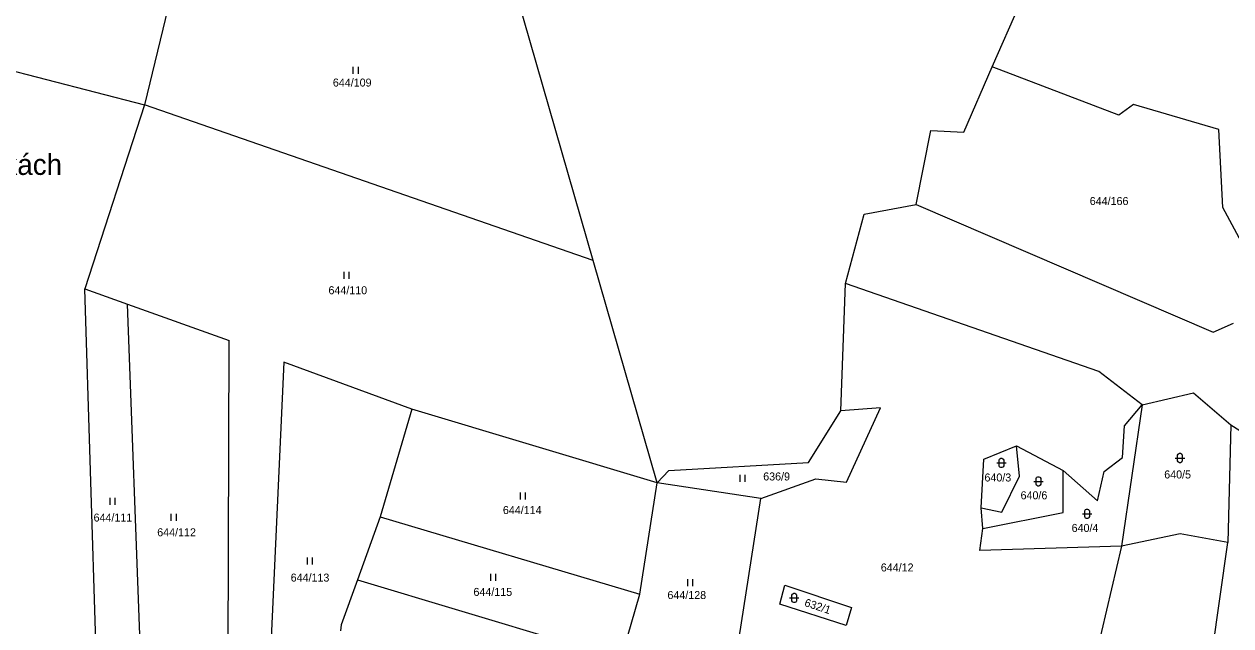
# Model space of a CAD drawing. Extents: x -791032 to -787751, y -1106872 to -1104403.
# Drawn here: x -789189 to -788932.6, y -1105599.2 to -1105471.5 of the extents above; entities that cross this region are included whole.
import ezdxf

# ---------------------------------------------------------------- set-up
doc = ezdxf.new("R2010")
doc.units = 0
for name, color, linetype in [('Vrstva 1', 7, 'Continuous'), ('Vrstva 14', 7, 'Continuous'), ('Vrstva 23', 7, 'Continuous'), ('Vrstva 39', 7, 'Continuous')]:
    doc.layers.add(name, color=color, linetype=linetype)

msp = doc.modelspace()

# ---------------------------------------------------------------- linework, layer by layer
at = {"layer": 'Vrstva 1'}
for p, q in [((-789146.23, -1105417.04), (-789163.41, -1105488.56)), ((-789068.11, -1105521.62), (-789084.1, -1105466)), ((-788983.32, -1105480.53), (-788977.5, -1105467.19)), ((-789221.79, -1105473.54), (-789163.41, -1105488.56)), ((-788989.37, -1105494.38), (-788983.32, -1105480.53)), ((-788956.44, -1105490.81), (-788983.32, -1105480.53)), ((-789163.41, -1105488.56), (-789176.09, -1105527.61)), ((-789068.11, -1105521.62), (-789163.41, -1105488.56)), ((-788953.33, -1105488.52), (-788956.44, -1105490.81)), ((-788935.16, -1105493.81), (-788953.33, -1105488.52)), ((-788999.5, -1105509.74), (-788996.37, -1105494.01)), ((-788996.37, -1105494.01), (-788989.37, -1105494.38)), ((-788934.33, -1105510.37), (-788935.16, -1105493.81)), ((-789010.51, -1105511.8), (-788999.5, -1105509.74)), ((-788999.5, -1105509.74), (-788936.39, -1105536.82)), ((-788925.08, -1105527.62), (-788934.33, -1105510.37)), ((-789014.53, -1105526.51), (-789010.51, -1105511.8)), ((-789054.54, -1105568.84), (-789068.11, -1105521.62)), ((-789015.5, -1105553.54), (-789014.53, -1105526.51)), ((-788960.67, -1105545.22), (-789014.53, -1105526.51)), ((-789176.09, -1105527.61), (-789167.02, -1105530.86)), ((-789173.21, -1105621.57), (-789176.09, -1105527.61)), ((-789163.6, -1105624.48), (-789167.02, -1105530.86)), ((-789167.02, -1105530.86), (-789145.48, -1105538.58)), ((-788936.39, -1105536.82), (-788932.05, -1105534.93)), ((-789145.77, -1105629.87), (-789145.48, -1105538.58)), ((-789133.84, -1105543.23), (-789137.95, -1105632.24)), ((-789106.67, -1105553.19), (-789133.84, -1105543.23)), ((-788951.45, -1105552.28), (-788960.67, -1105545.22)), ((-788951.45, -1105552.28), (-788940.6, -1105549.7)), ((-788940.6, -1105549.7), (-788932.67, -1105556.52)), ((-788951.45, -1105552.28), (-788955.9, -1105582.27)), ((-788955.22, -1105556.74), (-788951.45, -1105552.28)), ((-789106.67, -1105553.19), (-789113.4, -1105576.03)), ((-789054.54, -1105568.84), (-789106.67, -1105553.19)), ((-789022.35, -1105564.49), (-789015.5, -1105553.54)), ((-789007.06, -1105552.9), (-789015.5, -1105553.54)), ((-789014.27, -1105568.64), (-789007.06, -1105552.9)), ((-788955.67, -1105563.47), (-788955.22, -1105556.74)), ((-788932.67, -1105556.52), (-788933.29, -1105581.46)), ((-788932.67, -1105556.52), (-788924.39, -1105561.67)), ((-788985.13, -1105563.76), (-788978.18, -1105560.93)), ((-788977.52, -1105567.42), (-788978.18, -1105560.93)), ((-788978.18, -1105560.93), (-788968.25, -1105566.19)), ((-789052.03, -1105566.22), (-789022.35, -1105564.49)), ((-788985.68, -1105574.1), (-788985.13, -1105563.76)), ((-788959.53, -1105566.4), (-788955.67, -1105563.47)), ((-789054.54, -1105568.84), (-789052.03, -1105566.22)), ((-788981.32, -1105575.01), (-788977.52, -1105567.42)), ((-788968.27, -1105575.09), (-788968.25, -1105566.19)), ((-788968.25, -1105566.19), (-788960.99, -1105572.65)), ((-788960.99, -1105572.65), (-788959.53, -1105566.4)), ((-789058.19, -1105592.46), (-789054.54, -1105568.84)), ((-789032.47, -1105572.13), (-789054.54, -1105568.84)), ((-789032.47, -1105572.13), (-789020.83, -1105567.98)), ((-789020.83, -1105567.98), (-789014.27, -1105568.64)), ((-789038.51, -1105610.64), (-789032.47, -1105572.13)), ((-788985.33, -1105578.53), (-788985.68, -1105574.1)), ((-788985.68, -1105574.1), (-788981.32, -1105575.01)), ((-788985.33, -1105578.53), (-788968.27, -1105575.09)), ((-789113.4, -1105576.03), (-789118.21, -1105589.38)), ((-789113.4, -1105576.03), (-789058.19, -1105592.46)), ((-788985.96, -1105583.19), (-788985.33, -1105578.53)), ((-788943.38, -1105579.67), (-788955.9, -1105582.27)), ((-788933.29, -1105581.46), (-788943.38, -1105579.67)), ((-788955.9, -1105582.27), (-788985.96, -1105583.19)), ((-788955.9, -1105582.27), (-788969.53, -1105640.88)), ((-788941.4, -1105638.01), (-788933.29, -1105581.46)), ((-789118.21, -1105589.38), (-789121.66, -1105598.94)), ((-789118.21, -1105589.38), (-789073.82, -1105602.7)), ((-789028.45, -1105594.59), (-789027.41, -1105590.51)), ((-789027.41, -1105590.51), (-789013.24, -1105595.25)), ((-789061.77, -1105604.7), (-789058.19, -1105592.46)), ((-789014.39, -1105599.12), (-789028.45, -1105594.59)), ((-789013.24, -1105595.25), (-789014.39, -1105599.12)), ((-789121.66, -1105598.94), (-789121.78, -1105600.2))]:
    msp.add_line(p, q, dxfattribs=at)
at = {"layer": 'Vrstva 23'}
for p, q in [((-789119.07, -1105482.01), (-789119.07, -1105480.51)), ((-789118.07, -1105480.51), (-789118.07, -1105482.01)), ((-789120.99, -1105525.54), (-789120.99, -1105524.04)), ((-789119.99, -1105524.04), (-789119.99, -1105525.54)), ((-788943.75, -1105562.65), (-788943.55, -1105562.55)), ((-788943.55, -1105562.55), (-788943.35, -1105562.55)), ((-788943.35, -1105562.55), (-788943.15, -1105562.65)), ((-788982.39, -1105564.59), (-788980.39, -1105564.59)), ((-788981.89, -1105563.99), (-788981.79, -1105563.79)), ((-788981.89, -1105565.19), (-788981.89, -1105563.99)), ((-788981.79, -1105565.39), (-788981.89, -1105565.19)), ((-788981.79, -1105563.79), (-788981.69, -1105563.69)), ((-788981.69, -1105563.69), (-788981.49, -1105563.59)), ((-788981.49, -1105563.59), (-788981.29, -1105563.59)), ((-788981.29, -1105563.59), (-788981.09, -1105563.69)), ((-788981.09, -1105563.69), (-788980.99, -1105563.79)), ((-788980.99, -1105563.79), (-788980.89, -1105563.99)), ((-788980.89, -1105565.19), (-788980.99, -1105565.39)), ((-788980.89, -1105563.99), (-788980.89, -1105565.19)), ((-788944.45, -1105563.55), (-788942.45, -1105563.55)), ((-788943.95, -1105562.95), (-788943.85, -1105562.75)), ((-788943.95, -1105564.15), (-788943.95, -1105562.95)), ((-788943.85, -1105564.35), (-788943.95, -1105564.15)), ((-788943.85, -1105562.75), (-788943.75, -1105562.65)), ((-788943.75, -1105564.45), (-788943.85, -1105564.35)), ((-788943.55, -1105564.55), (-788943.75, -1105564.45)), ((-788943.35, -1105564.55), (-788943.55, -1105564.55)), ((-788943.15, -1105564.45), (-788943.35, -1105564.55)), ((-788943.15, -1105562.65), (-788943.05, -1105562.75)), ((-788943.05, -1105564.35), (-788943.15, -1105564.45)), ((-788943.05, -1105562.75), (-788942.95, -1105562.95)), ((-788942.95, -1105564.15), (-788943.05, -1105564.35)), ((-788942.95, -1105562.95), (-788942.95, -1105564.15)), ((-789036.86, -1105568.63), (-789036.86, -1105567.13)), ((-789035.86, -1105567.13), (-789035.86, -1105568.63)), ((-788981.69, -1105565.49), (-788981.79, -1105565.39)), ((-788981.49, -1105565.59), (-788981.69, -1105565.49)), ((-788981.29, -1105565.59), (-788981.49, -1105565.59)), ((-788981.09, -1105565.49), (-788981.29, -1105565.59)), ((-788980.99, -1105565.39), (-788981.09, -1105565.49)), ((-788974.03, -1105567.91), (-788973.93, -1105567.71)), ((-788973.93, -1105567.71), (-788973.83, -1105567.61)), ((-788973.83, -1105567.61), (-788973.63, -1105567.51)), ((-788973.63, -1105567.51), (-788973.43, -1105567.51)), ((-788973.43, -1105567.51), (-788973.23, -1105567.61)), ((-788973.23, -1105567.61), (-788973.13, -1105567.71)), ((-788973.13, -1105567.71), (-788973.03, -1105567.91)), ((-788974.53, -1105568.51), (-788972.53, -1105568.51)), ((-788974.03, -1105569.11), (-788974.03, -1105567.91)), ((-788973.93, -1105569.31), (-788974.03, -1105569.11)), ((-788973.83, -1105569.41), (-788973.93, -1105569.31)), ((-788973.63, -1105569.51), (-788973.83, -1105569.41)), ((-788973.43, -1105569.51), (-788973.63, -1105569.51)), ((-788973.23, -1105569.41), (-788973.43, -1105569.51)), ((-788973.13, -1105569.31), (-788973.23, -1105569.41)), ((-788973.03, -1105569.11), (-788973.13, -1105569.31)), ((-788973.03, -1105567.91), (-788973.03, -1105569.11)), ((-789170.74, -1105573.52), (-789170.74, -1105572.02)), ((-789169.74, -1105572.02), (-789169.74, -1105573.52)), ((-789083.58, -1105572.37), (-789083.58, -1105570.87)), ((-789082.58, -1105570.87), (-789082.58, -1105572.37)), ((-789157.74, -1105576.91), (-789157.74, -1105575.41)), ((-789156.74, -1105575.41), (-789156.74, -1105576.91)), ((-788964.19, -1105575.39), (-788962.19, -1105575.39)), ((-788963.69, -1105574.79), (-788963.59, -1105574.59)), ((-788963.69, -1105575.99), (-788963.69, -1105574.79)), ((-788963.59, -1105574.59), (-788963.49, -1105574.49)), ((-788963.49, -1105574.49), (-788963.29, -1105574.39)), ((-788963.29, -1105574.39), (-788963.09, -1105574.39)), ((-788963.09, -1105574.39), (-788962.89, -1105574.49)), ((-788962.89, -1105574.49), (-788962.79, -1105574.59)), ((-788962.79, -1105574.59), (-788962.69, -1105574.79)), ((-788962.69, -1105574.79), (-788962.69, -1105575.99)), ((-788963.59, -1105576.19), (-788963.69, -1105575.99)), ((-788963.49, -1105576.29), (-788963.59, -1105576.19)), ((-788963.29, -1105576.39), (-788963.49, -1105576.29)), ((-788963.09, -1105576.39), (-788963.29, -1105576.39)), ((-788962.89, -1105576.29), (-788963.09, -1105576.39)), ((-788962.79, -1105576.19), (-788962.89, -1105576.29)), ((-788962.69, -1105575.99), (-788962.79, -1105576.19)), ((-789128.82, -1105586.15), (-789128.82, -1105584.65)), ((-789127.82, -1105584.65), (-789127.82, -1105586.15)), ((-789089.88, -1105589.61), (-789089.88, -1105588.11)), ((-789088.88, -1105588.11), (-789088.88, -1105589.61)), ((-789048.01, -1105590.78), (-789048.01, -1105589.28)), ((-789047.01, -1105589.28), (-789047.01, -1105590.78)), ((-789026.39, -1105593.25), (-789024.39, -1105593.25)), ((-789025.89, -1105592.65), (-789025.79, -1105592.45)), ((-789025.89, -1105593.85), (-789025.89, -1105592.65)), ((-789025.79, -1105592.45), (-789025.69, -1105592.35)), ((-789025.69, -1105592.35), (-789025.49, -1105592.25)), ((-789025.49, -1105592.25), (-789025.29, -1105592.25)), ((-789025.29, -1105592.25), (-789025.09, -1105592.35)), ((-789025.09, -1105592.35), (-789024.99, -1105592.45)), ((-789024.99, -1105592.45), (-789024.89, -1105592.65)), ((-789024.89, -1105592.65), (-789024.89, -1105593.85)), ((-789025.79, -1105594.05), (-789025.89, -1105593.85)), ((-789025.69, -1105594.15), (-789025.79, -1105594.05)), ((-789025.49, -1105594.25), (-789025.69, -1105594.15)), ((-789025.29, -1105594.25), (-789025.49, -1105594.25)), ((-789025.09, -1105594.15), (-789025.29, -1105594.25)), ((-789024.99, -1105594.05), (-789025.09, -1105594.15)), ((-789024.89, -1105593.85), (-789024.99, -1105594.05))]:
    msp.add_line(p, q, dxfattribs=at)

# ---------------------------------------------------------------- texts
at = {"layer": 'Vrstva 14'}
for s, p in [('644/109', (-789123.414, -1105484.71)), ('644/166', (-788962.615, -1105509.85)), ('644/110', (-789124.347, -1105528.79)), ('636/9', (-789031.99, -1105568.31)), ('640/3', (-788984.985, -1105568.53)), ('640/5', (-788946.791, -1105567.89)), ('640/6', (-788977.315, -1105572.31)), ('644/111', (-789174.251, -1105577.04)), ('644/114', (-789087.294, -1105575.44)), ('640/4', (-788966.471, -1105579.24)), ('644/112', (-789160.728, -1105580.16)), ('644/113', (-789132.378, -1105589.78)), ('644/12', (-789007.005, -1105587.63)), ('644/115', (-789093.544, -1105592.82)), ('644/128', (-789052.334, -1105593.48))]:
    msp.add_text(s, height=1.7, dxfattribs=at).set_placement(p)
msp.add_text('632/1', height=1.7, rotation=341.8299, dxfattribs=at).set_placement((-789023.37, -1105594.932))
at = {"layer": 'Vrstva 39'}
msp.add_text('V trávníkách', height=4.4, dxfattribs=at).set_placement((-789213.66, -1105503.46))

doc.saveas('drawing.dxf')
